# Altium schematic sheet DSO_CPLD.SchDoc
size A4
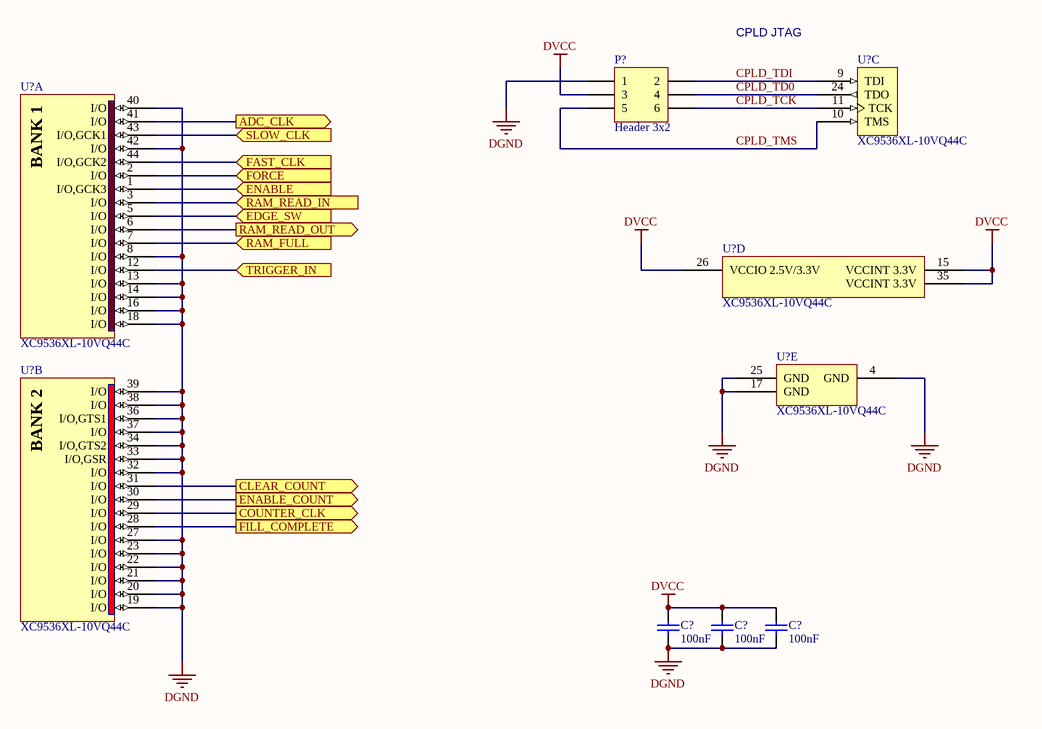
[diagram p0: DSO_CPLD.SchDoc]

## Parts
(Parts that share a designator on the sheet are numbered #1, #2 ... from top to bottom, then left to right.)
C?#1  100nF  [0805C]
C?#2  100nF  [0805C]
C?#3  100nF  [0805C]
P?  Header 3x2  [HDR3x2]
U?#1  XC9536XL-10VQ44C  [VQ44_L]  (part C of 5)
U?#2  XC9536XL-10VQ44C  [VQ44_L]  (part A of 5)
U?#3  XC9536XL-10VQ44C  [VQ44_L]  (part D of 5)
U?#4  XC9536XL-10VQ44C  [VQ44_L]  (part E of 5)
U?#5  XC9536XL-10VQ44C  [VQ44_L]  (part B of 5)

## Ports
ADC_CLK (out), CLEAR_COUNT (out), COUNTER_CLK (out), EDGE_SW (in), ENABLE (in), ENABLE_COUNT (out), FAST_CLK (in), FILL_COMPLETE (out), FORCE (in), RAM_FULL (in), RAM_READ_IN (in), RAM_READ_OUT (out), SLOW_CLK (in), TRIGGER_IN (in)

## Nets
DGND: C?#1.2 C?#2.2 C?#3.2 P?.1 U?#2.8(I/O) U?#2.13(I/O) U?#2.14(I/O) U?#2.16(I/O) U?#2.18(I/O) U?#2.40(I/O) U?#2.42(I/O) U?#4.4(GND) U?#4.17(GND) U?#4.25(GND) U?#5.19(I/O) U?#5.20(I/O) U?#5.21(I/O) U?#5.22(I/O) U?#5.23(I/O) U?#5.27(I/O) U?#5.32(I/O) U?#5.33(I/O,GSR) U?#5.34(I/O,GTS2) U?#5.36(I/O,GTS1) U?#5.37(I/O) U?#5.38(I/O) U?#5.39(I/O)
DVCC: C?#1.1 C?#2.1 C?#3.1 P?.3 U?#3.15(VCCINT_3.3V) U?#3.26(VCCIO_2.5V/3.3V) U?#3.35(VCCINT_3.3V)
ADC_CLK: U?#2.41(I/O) ; port ADC_CLK
CLEAR_COUNT: U?#5.31(I/O) ; port CLEAR_COUNT
COUNTER_CLK: U?#5.29(I/O) ; port COUNTER_CLK
CPLD_TCK: P?.6 U?#1.11(TCK)
CPLD_TD0: P?.4 U?#1.24(TDO)
CPLD_TDI: P?.2 U?#1.9(TDI)
CPLD_TMS: P?.5 U?#1.10(TMS)
EDGE_SW: U?#2.5(I/O) ; port EDGE_SW
ENABLE: U?#2.1(I/O,GCK3) ; port ENABLE
ENABLE_COUNT: U?#5.30(I/O) ; port ENABLE_COUNT
FAST_CLK: U?#2.44(I/O,GCK2) ; port FAST_CLK
FILL_COMPLETE: U?#5.28(I/O) ; port FILL_COMPLETE
FORCE: U?#2.2(I/O) ; port FORCE
RAM_FULL: U?#2.7(I/O) ; port RAM_FULL
RAM_READ_IN: U?#2.3(I/O) ; port RAM_READ_IN
RAM_READ_OUT: U?#2.6(I/O) ; port RAM_READ_OUT
SLOW_CLK: U?#2.43(I/O,GCK1) ; port SLOW_CLK
TRIGGER_IN: U?#2.12(I/O) ; port TRIGGER_IN

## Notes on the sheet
- CPLD JTAG

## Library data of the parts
C?#1-C?#3 = C: Capacitor; Reviewed by: RM - 2018/08/05
P? = Header 3x2: Header, 5-Pin; Reviewed by: RM - 2018/08/05
U?#1-U?#5 = XC9536XL-10VQG44C: FastFLASH XC900XL, 3.3V High-Performance 36 Macrocell CPLD, 34 User I/Os, 44-Pin VQFP, Speed Grade 10, Commercial Grade; Reviewed by: RM - 2018/08/05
